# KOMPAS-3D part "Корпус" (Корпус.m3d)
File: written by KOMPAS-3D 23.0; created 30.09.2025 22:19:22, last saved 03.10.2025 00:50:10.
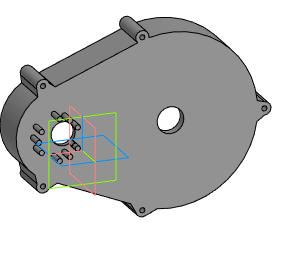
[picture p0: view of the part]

Document properties: Автор: Inspektor_Kot; Полное имя файла: I:\Autodesk Inventor Projects\ИМ-ИТ ЦД\Вариант 11\Корпус.m3d

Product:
- Part/product: Корпус
    Масса: 0.847568

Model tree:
1. Эскиз:1  (with: Операция без истории:1)  (labels: Движок 12В)
2. Элемент выдавливания:1  (with: Операция без истории:1)
     Расстояние 1 = -12
3. Эскиз:2  (with: Элемент выдавливания:1, Элемент выдавливания:2)  (labels: Цилиндрическое зубчатое зацепление1\Шестерёнка большая)
4. Элемент выдавливания:2
     Расстояние 1 = 4
5. Эскиз:3  (with: Элемент выдавливания:2, Элемент выдавливания:1)  (labels: Цилиндрическое зубчатое зацепление1\Шестерёнка большая)
6. Элемент выдавливания:3  (with: Операция без истории:1)  (labels: Цилиндрическое зубчатое зацепление1\Шестерёнка большая)
     Расстояние 1 = 3
7. Эскиз:4  (with: Элемент выдавливания:2)
8. Элемент выдавливания:4
     Расстояние 1 = 28
9. Эскиз:5  (with: Элемент выдавливания:2, Элемент выдавливания:4)
10. Элемент выдавливания:5  (with: Элемент выдавливания:4)
     Расстояние 1 = -32
11. Эскиз:8  (with: Элемент выдавливания:2)
12. Элемент выдавливания:8
     Расстояние 2 = 10

Referenced files in I:\Autodesk Inventor Projects\ИМ-ИТ ЦД\Вариант 7\: Мотор-редуктор.a3d
Referenced files in I:\Autodesk Inventor Projects\ИМ-ИТ ЦД\Вариант 11\: Мотор-редуктор.a3d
